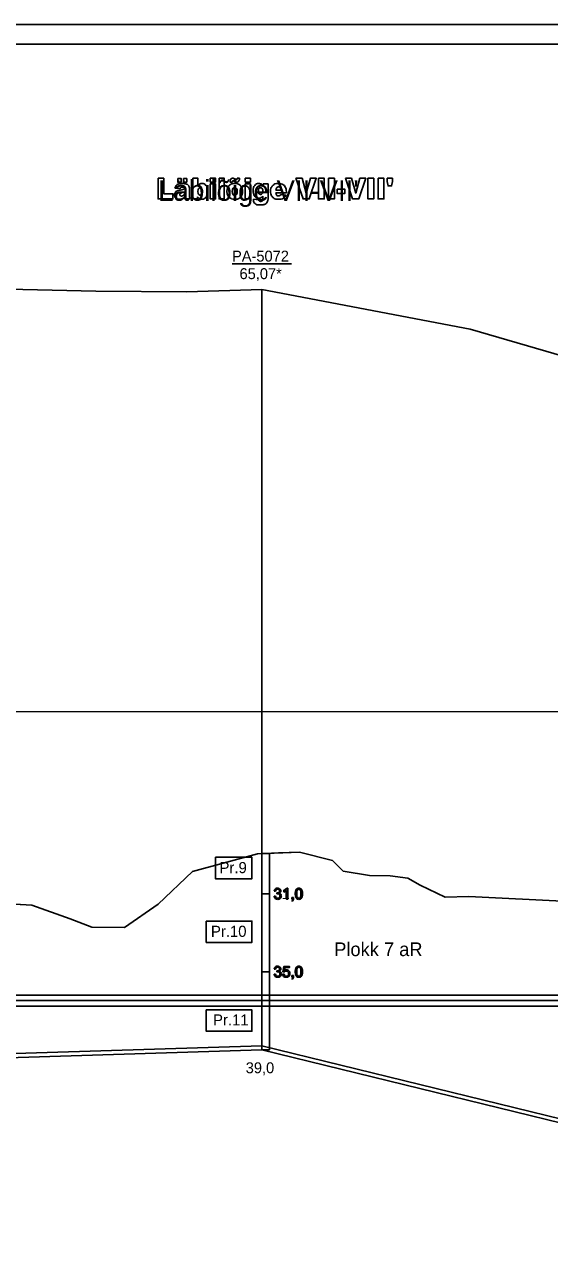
# Model space of a CAD drawing. Extents: x 700746 to 706058, y 6570320 to 6580460.
# Drawn here: x 704794 to 705063, y 6574741 to 6575370 of the extents above; entities that cross this region are included whole.
import ezdxf

# ---------------------------------------------------------------- set-up
doc = ezdxf.new("R2010")
doc.units = 0
for name, color, linetype in [('ABIJOONIS', 7, 'Continuous'), ('GEOLPUNKT', 7, 'Continuous'), ('GEOLPUNKT_proovid', 7, 'Continuous'), ('Lõige', 7, 'Continuous'), ('Maapind', 7, 'Continuous'), ('PIIR', 7, 'Continuous'), ('Plokid', 7, 'Continuous'), ('Täide', 7, 'Continuous'), ('VEEKOGU', 7, 'Continuous'), ('VORMISTUS', 7, 'Continuous')]:
    doc.layers.add(name, color=color, linetype=linetype)

# ---------------------------------------------------------------- blocks, each defined once
blk = doc.blocks.new("Läbilõige VII-VII'")
at = {"layer": 'Lõige'}
for points in [[(-30.27, 3.15), (-28.79, 3.15), (-28.79, -0.84), (-26.47, -0.84), (-26.47, -2.15), (-30.27, -2.15), (-30.27, 3.15)], [(-21.39, 3.15), (-20.05, 3.15), (-20.05, 1.31)], [(-20.15, -1.58), (-20.15, -2.15), (-21.39, -2.15), (-21.39, 3.15)], [(-16.88, 3.15), (-15.54, 3.15), (-15.54, 2.15), (-16.88, 2.15), (-16.88, 3.15)], [(-14.65, 3.15), (-13.31, 3.15), (-13.31, -2.15), (-14.65, -2.15), (-14.65, 3.15)], [(-9.96, 3.16), (-9.44, 3.16)], [(-7.93, 3.15), (-6.59, 3.15), (-6.59, 2.15), (-7.93, 2.15), (-7.93, 3.15)], [(5.06, 3.15), (6.61, 3.15), (7.69, -0.66), (8.76, 3.15), (10.26, 3.15), (8.48, -2.15), (6.87, -2.15), (5.06, 3.15)], [(10.81, 3.15), (12.3, 3.15), (12.3, -2.15), (10.81, -2.15), (10.81, 3.15)], [(13.42, 3.15), (14.91, 3.15), (14.91, -2.15), (13.42, -2.15), (13.42, 3.15)], [(17.73, 3.15), (19.29, 3.15), (20.37, -0.66), (21.44, 3.15), (22.94, 3.15), (21.16, -2.15), (19.55, -2.15), (17.73, 3.15)], [(23.49, 3.15), (24.98, 3.15), (24.98, -2.15), (23.49, -2.15), (23.49, 3.15)], [(26.1, 3.15), (27.59, 3.15), (27.59, -2.15), (26.1, -2.15), (26.1, 3.15)], [(28.44, 3.15), (29.77, 3.15), (29.77, 2.28), (29.56, 1.2), (28.66, 1.2), (28.44, 2.28), (28.44, 3.15)], [(-24.66, 0.44), (-25.94, 0.59)], [(-25.17, 3.08), (-24.32, 3.08), (-24.32, 2.18), (-25.17, 2.18), (-25.17, 3.08)], [(-23.79, 3.08), (-22.93, 3.08), (-22.93, 2.18), (-23.79, 2.18), (-23.79, 3.08)], [(-22.21, 0.36), (-22.21, -1.33)], [(-16.88, 1.69), (-15.54, 1.69), (-15.54, -2.15), (-16.88, -2.15), (-16.88, 1.69)], [(-11.29, 2.16), (-11.8, 2.16)], [(-7.93, 1.69), (-6.59, 1.69), (-6.59, -2.15), (-7.93, -2.15), (-7.93, 1.69)], [(-3.32, 1.69), (-2.07, 1.69), (-2.07, -1.93), (-2.07, -2.1)], [(-3.32, 1.12), (-3.32, 1.69)], [(-0.07, 0.11), (1.24, 0.11)], [(15.63, 0.35), (17.57, 0.35), (17.57, -0.79), (15.63, -0.79), (15.63, 0.35)], [(-23.51, -0.56), (-23.51, -0.33)], [(-22.04, -2.15), (-23.29, -2.15)], [(-5.8, -2.24), (-4.51, -2.4)], [(-3.42, -2.02), (-3.42, -1.44)], [(2.6, -0.59), (-0.07, -0.59)], [(1.21, -1.02), (2.52, -1.16)], [(2.6, -0.43), (2.6, -0.59)]]:
    blk.add_lwpolyline(points, dxfattribs=at)
for points in [[(-11.8, 2.16), (-11.8, 2.25), (-11.8, 2.31), (-11.8, 2.7), (-11.61, 2.93), (-11.42, 3.16), (-11.15, 3.16), (-11.04, 3.16), (-10.94, 3.13), (-10.83, 3.1), (-10.56, 2.97), (-10.29, 2.84), (-10.16, 2.84), (-10.08, 2.84), (-10.02, 2.91), (-9.97, 2.98), (-9.96, 3.16)], [(-9.44, 3.16), (-9.44, 3.06), (-9.44, 2.99), (-9.44, 2.59), (-9.62, 2.37), (-9.81, 2.15), (-10.09, 2.15), (-10.3, 2.15), (-10.73, 2.34), (-10.99, 2.46), (-11.08, 2.46), (-11.18, 2.46), (-11.23, 2.39), (-11.28, 2.33), (-11.29, 2.16)], [(-23.29, -2.15), (-23.37, -2), (-23.39, -1.92), (-23.41, -1.85), (-23.44, -1.68), (-23.7, -1.96), (-23.96, -2.08), (-24.31, -2.24), (-24.78, -2.24), (-25.4, -2.24), (-25.72, -1.92), (-26.04, -1.6), (-26.04, -1.14), (-26.04, -0.7), (-25.81, -0.42), (-25.58, -0.13), (-24.95, 0), (-24.2, 0.17), (-23.98, 0.24), (-23.76, 0.3), (-23.51, 0.41), (-23.51, 0.68), (-23.61, 0.79), (-23.71, 0.9), (-23.97, 0.9), (-24.29, 0.9), (-24.46, 0.78), (-24.58, 0.69), (-24.66, 0.44)], [(-25.94, 0.59), (-25.86, 0.96), (-25.73, 1.17), (-25.59, 1.39), (-25.34, 1.54), (-25.15, 1.65), (-24.83, 1.72), (-24.51, 1.78), (-24.14, 1.78), (-23.54, 1.78), (-23.18, 1.7), (-22.82, 1.63), (-22.57, 1.39), (-22.4, 1.23), (-22.31, 0.93), (-22.21, 0.63), (-22.21, 0.36)], [(-20.05, 1.31), (-19.85, 1.55), (-19.6, 1.66), (-19.34, 1.78), (-19.04, 1.78), (-18.4, 1.78), (-17.99, 1.27), (-17.57, 0.77), (-17.57, -0.18), (-17.57, -0.8), (-17.76, -1.28), (-17.95, -1.76), (-18.28, -2), (-18.62, -2.24), (-19.03, -2.24), (-19.38, -2.24), (-19.67, -2.07), (-19.89, -1.94), (-20.15, -1.58)], [(-20.06, -0.22), (-20.06, -0.72), (-19.89, -0.94), (-19.72, -1.16), (-19.47, -1.16), (-19.23, -1.16), (-19.07, -0.94), (-18.9, -0.72), (-18.9, -0.21), (-18.9, 0.25), (-19.06, 0.46), (-19.22, 0.68), (-19.45, 0.68), (-19.72, 0.68), (-19.89, 0.45), (-20.06, 0.23), (-20.06, -0.22)], [(-12.62, -0.24), (-12.62, 0.64), (-12.08, 1.21), (-11.54, 1.78), (-10.63, 1.78), (-9.59, 1.78), (-9.05, 1.11), (-8.63, 0.57), (-8.63, -0.22), (-8.63, -1.1), (-9.16, -1.67), (-9.69, -2.24), (-10.63, -2.24), (-11.47, -2.24), (-11.98, -1.77), (-12.62, -1.18), (-12.62, -0.24)], [(-11.28, -0.24), (-11.28, -0.75), (-11.09, -1), (-10.91, -1.24), (-10.62, -1.24), (-10.33, -1.24), (-10.15, -1), (-9.97, -0.76), (-9.97, -0.22), (-9.97, 0.28), (-10.15, 0.52), (-10.34, 0.76), (-10.61, 0.76), (-10.9, 0.76), (-11.09, 0.52), (-11.28, 0.27), (-11.28, -0.24)], [(-3.42, -1.44), (-3.62, -1.7), (-3.81, -1.82), (-4.12, -2), (-4.48, -2), (-5.17, -2), (-5.6, -1.32), (-5.9, -0.85), (-5.9, -0.06), (-5.9, 0.84), (-5.51, 1.31), (-5.12, 1.78), (-4.49, 1.78), (-4.08, 1.78), (-3.82, 1.63), (-3.55, 1.47), (-3.32, 1.12)], [(-4.57, -0.17), (-4.57, -0.59), (-4.41, -0.79), (-4.25, -0.99), (-3.99, -0.99), (-3.75, -0.99), (-3.58, -0.78), (-3.41, -0.58), (-3.41, -0.15), (-3.41, 0.27), (-3.59, 0.49), (-3.76, 0.71), (-4.02, 0.71), (-4.27, 0.71), (-4.42, 0.51), (-4.57, 0.3), (-4.57, -0.17)], [(2.52, -1.16), (2.22, -1.73), (1.79, -1.99), (1.37, -2.24), (0.57, -2.24), (-0.12, -2.24), (-0.52, -2.02), (-0.91, -1.81), (-1.17, -1.34), (-1.43, -0.87), (-1.43, -0.24), (-1.43, 0.66), (-0.91, 1.22), (-0.39, 1.78), (0.53, 1.78), (1.28, 1.78), (1.71, 1.53), (2.14, 1.28), (2.37, 0.81), (2.6, 0.33), (2.6, -0.43)], [(1.24, 0.11), (1.2, 0.54), (1.03, 0.72), (0.86, 0.91), (0.59, 0.91), (0.27, 0.91), (0.08, 0.63), (-0.04, 0.45), (-0.07, 0.11)], [(-23.51, -0.33), (-23.79, -0.44), (-24.08, -0.52), (-24.49, -0.64), (-24.6, -0.76), (-24.71, -0.87), (-24.71, -1.03), (-24.71, -1.2), (-24.6, -1.31), (-24.49, -1.42), (-24.28, -1.42), (-24.05, -1.42), (-23.86, -1.3), (-23.67, -1.18), (-23.59, -1.01), (-23.51, -0.84), (-23.51, -0.56)], [(-22.21, -1.33), (-22.21, -1.6), (-22.18, -1.76), (-22.15, -1.91), (-22.04, -2.15)], [(-2.07, -2.1), (-2.07, -2.47), (-2.21, -2.79), (-2.35, -3.12), (-2.58, -3.32), (-2.81, -3.53), (-3.17, -3.62), (-3.52, -3.71), (-3.98, -3.71), (-5.03, -3.71), (-5.42, -3.36), (-5.81, -3.01), (-5.81, -2.43), (-5.81, -2.36), (-5.8, -2.24)], [(-4.51, -2.4), (-4.46, -2.6), (-4.36, -2.67), (-4.21, -2.78), (-3.99, -2.78), (-3.7, -2.78), (-3.56, -2.61), (-3.42, -2.44), (-3.42, -2.02)], [(-0.07, -0.59), (-0.04, -0.95), (0.1, -1.12), (0.29, -1.37), (0.6, -1.37), (0.8, -1.37), (0.98, -1.27), (1.09, -1.2), (1.21, -1.02)]]:
    blk.add_open_spline(points, degree=3, dxfattribs=at)
blk.add_text("Läbilõige VII-VII'", height=5.3, dxfattribs=at).set_placement((-30.26, -2.65))

msp = doc.modelspace()

# ---------------------------------------------------------------- linework, layer by layer
at = {"layer": 'ABIJOONIS'}
msp.add_lwpolyline([(704017.06, 6575370.2), (705897.06, 6575370.2), (705897.06, 6574500.2), (704017.06, 6574500.2), (704017.06, 6575370.2)], dxfattribs=at)
at = {"layer": 'GEOLPUNKT'}
for p, q in [((704900.75, 6575247.41), (704931.19, 6575247.41)), ((704915.95, 6575234.43), (704915.95, 6574945.02)), ((704915.95, 6574945.02), (704915.95, 6574844.43))]:
    msp.add_line(p, q, dxfattribs=at)
at = {"layer": 'GEOLPUNKT_proovid'}
for points in [[(704915.95, 6574945.02), (704919.95, 6574945.02), (704919.95, 6574924.43), (704915.95, 6574924.43)], [(704892.25, 6574943.09), (704910.95, 6574943.09), (704910.95, 6574932.13), (704892.25, 6574932.13)], [(704915.95, 6574924.43), (704919.95, 6574924.43), (704919.95, 6574884.43), (704915.95, 6574884.43)], [(704887.53, 6574910.38), (704910.95, 6574910.38), (704910.95, 6574899.42), (704887.53, 6574899.42)], [(704915.95, 6574884.43), (704919.95, 6574884.43), (704919.95, 6574844.43), (704915.95, 6574844.43)], [(704887.53, 6574864.86), (704910.95, 6574864.86), (704910.95, 6574853.9), (704887.53, 6574853.9)]]:
    msp.add_lwpolyline(points, close=True, dxfattribs=at)
for points in [[(704923.08, 6574925.68), (704922.39, 6574925.8)], [(704927.2, 6574925.18), (704927.2, 6574925.84)], [(704929.26, 6574921.63), (704928.57, 6574921.63), (704928.57, 6574926.01)], [(704928.81, 6574927.25), (704929.26, 6574927.25), (704929.26, 6574921.63)], [(704922.33, 6574923.11), (704923.01, 6574923.2)], [(704923.68, 6574924.28), (704923.76, 6574924.89)], [(704931.54, 6574920.52), (704931.34, 6574920.81)], [(704931.39, 6574921.63), (704931.39, 6574922.41), (704932.17, 6574922.41), (704932.17, 6574921.63)], [(704931.78, 6574921.63), (704931.39, 6574921.63)], [(704922.33, 6574883.11), (704923.01, 6574883.2)], [(704923.08, 6574885.68), (704922.39, 6574885.8)], [(704923.68, 6574884.28), (704923.76, 6574884.89)], [(704926.67, 6574883.1), (704927.39, 6574883.16)], [(704927.44, 6574884.19), (704926.79, 6574884.28), (704927.34, 6574887.16), (704930.12, 6574887.16), (704930.12, 6574886.5), (704927.89, 6574886.5), (704927.58, 6574885)], [(704931.39, 6574881.63), (704931.39, 6574882.41), (704932.17, 6574882.41), (704932.17, 6574881.63)], [(704931.54, 6574880.52), (704931.34, 6574880.81)], [(704931.78, 6574881.63), (704931.39, 6574881.63)]]:
    msp.add_lwpolyline(points, dxfattribs=at)
for points in [[(704922.39, 6574925.8), (704922.52, 6574926.49), (704922.97, 6574926.87), (704923.41, 6574927.25), (704924.08, 6574927.25), (704924.54, 6574927.25), (704924.92, 6574927.05), (704925.31, 6574926.86), (704925.51, 6574926.52), (704925.72, 6574926.18), (704925.72, 6574925.8), (704925.72, 6574925.44), (704925.52, 6574925.14), (704925.33, 6574924.84), (704924.95, 6574924.66), (704925.44, 6574924.55), (704925.72, 6574924.19), (704925.99, 6574923.83), (704925.99, 6574923.29), (704925.99, 6574922.55), (704925.46, 6574922.04), (704924.92, 6574921.54), (704924.11, 6574921.54), (704923.37, 6574921.54), (704922.88, 6574921.97), (704922.39, 6574922.41), (704922.33, 6574923.11)], [(704923.76, 6574924.89), (704923.83, 6574924.88), (704923.87, 6574924.88), (704924.31, 6574924.88), (704924.66, 6574925.11), (704925.01, 6574925.34), (704925.01, 6574925.81), (704925.01, 6574926.19), (704924.75, 6574926.44), (704924.5, 6574926.69), (704924.09, 6574926.69), (704923.69, 6574926.69), (704923.42, 6574926.43), (704923.16, 6574926.18), (704923.08, 6574925.68)], [(704927.2, 6574925.84), (704927.77, 6574926.12), (704928.2, 6574926.5), (704928.64, 6574926.89), (704928.81, 6574927.25)], [(704928.57, 6574926.01), (704928.32, 6574925.77), (704927.92, 6574925.54), (704927.52, 6574925.3), (704927.2, 6574925.18)], [(704933.19, 6574924.39), (704933.19, 6574925.38), (704933.4, 6574925.99), (704933.6, 6574926.6), (704934, 6574926.92), (704934.41, 6574927.25), (704935.02, 6574927.25), (704935.47, 6574927.25), (704935.81, 6574927.07), (704936.15, 6574926.89), (704936.37, 6574926.55), (704936.59, 6574926.2), (704936.72, 6574925.71), (704936.84, 6574925.22), (704936.84, 6574924.39), (704936.84, 6574923.41), (704936.64, 6574922.8), (704936.44, 6574922.19), (704936.03, 6574921.86), (704935.63, 6574921.54), (704935.02, 6574921.54), (704934.21, 6574921.54), (704933.75, 6574922.11), (704933.19, 6574922.81), (704933.19, 6574924.39)], [(704933.9, 6574924.39), (704933.9, 6574923.01), (704934.22, 6574922.55), (704934.55, 6574922.1), (704935.02, 6574922.1), (704935.49, 6574922.1), (704935.81, 6574922.56), (704936.13, 6574923.01), (704936.13, 6574924.39), (704936.13, 6574925.77), (704935.81, 6574926.23), (704935.49, 6574926.68), (704935.01, 6574926.68), (704934.54, 6574926.68), (704934.25, 6574926.28), (704933.9, 6574925.77), (704933.9, 6574924.39)], [(704923.01, 6574923.2), (704923.13, 6574922.62), (704923.41, 6574922.36), (704923.7, 6574922.1), (704924.11, 6574922.1), (704924.6, 6574922.1), (704924.93, 6574922.44), (704925.26, 6574922.77), (704925.26, 6574923.27), (704925.26, 6574923.75), (704924.95, 6574924.05), (704924.64, 6574924.36), (704924.17, 6574924.36), (704923.97, 6574924.36), (704923.68, 6574924.28)], [(704931.34, 6574920.81), (704931.56, 6574920.91), (704931.67, 6574921.1), (704931.77, 6574921.28), (704931.78, 6574921.63)], [(704932.17, 6574921.63), (704932.17, 6574921.2), (704932.02, 6574920.93), (704931.87, 6574920.66), (704931.54, 6574920.52)], [(704922.39, 6574885.8), (704922.52, 6574886.49), (704922.97, 6574886.87), (704923.41, 6574887.25), (704924.08, 6574887.25), (704924.54, 6574887.25), (704924.92, 6574887.05), (704925.31, 6574886.86), (704925.51, 6574886.52), (704925.72, 6574886.18), (704925.72, 6574885.8), (704925.72, 6574885.44), (704925.52, 6574885.14), (704925.33, 6574884.84), (704924.95, 6574884.66), (704925.44, 6574884.55), (704925.72, 6574884.19), (704925.99, 6574883.83), (704925.99, 6574883.29), (704925.99, 6574882.55), (704925.46, 6574882.04), (704924.92, 6574881.54), (704924.11, 6574881.54), (704923.37, 6574881.54), (704922.88, 6574881.97), (704922.39, 6574882.41), (704922.33, 6574883.11)], [(704923.01, 6574883.2), (704923.13, 6574882.62), (704923.41, 6574882.36), (704923.7, 6574882.1), (704924.11, 6574882.1), (704924.6, 6574882.1), (704924.93, 6574882.44), (704925.26, 6574882.77), (704925.26, 6574883.27), (704925.26, 6574883.75), (704924.95, 6574884.05), (704924.64, 6574884.36), (704924.17, 6574884.36), (704923.97, 6574884.36), (704923.68, 6574884.28)], [(704923.76, 6574884.89), (704923.83, 6574884.88), (704923.87, 6574884.88), (704924.31, 6574884.88), (704924.66, 6574885.11), (704925.01, 6574885.34), (704925.01, 6574885.81), (704925.01, 6574886.19), (704924.75, 6574886.44), (704924.5, 6574886.69), (704924.09, 6574886.69), (704923.69, 6574886.69), (704923.42, 6574886.43), (704923.16, 6574886.18), (704923.08, 6574885.68)], [(704927.58, 6574885), (704928.09, 6574885.35), (704928.64, 6574885.35), (704929.38, 6574885.35), (704929.88, 6574884.84), (704930.38, 6574884.33), (704930.38, 6574883.53), (704930.38, 6574882.77), (704929.94, 6574882.22), (704929.4, 6574881.54), (704928.47, 6574881.54), (704927.71, 6574881.54), (704927.22, 6574881.96), (704926.74, 6574882.39), (704926.67, 6574883.1)], [(704927.39, 6574883.16), (704927.47, 6574882.63), (704927.76, 6574882.36), (704928.05, 6574882.1), (704928.47, 6574882.1), (704928.97, 6574882.1), (704929.31, 6574882.47), (704929.65, 6574882.85), (704929.65, 6574883.47), (704929.65, 6574884.06), (704929.33, 6574884.4), (704929, 6574884.74), (704928.46, 6574884.74), (704928.12, 6574884.74), (704927.86, 6574884.59), (704927.59, 6574884.44), (704927.44, 6574884.19)], [(704933.19, 6574884.39), (704933.19, 6574885.38), (704933.4, 6574885.99), (704933.6, 6574886.6), (704934, 6574886.92), (704934.41, 6574887.25), (704935.02, 6574887.25), (704935.47, 6574887.25), (704935.81, 6574887.07), (704936.15, 6574886.89), (704936.37, 6574886.55), (704936.59, 6574886.2), (704936.72, 6574885.71), (704936.84, 6574885.22), (704936.84, 6574884.39), (704936.84, 6574883.41), (704936.64, 6574882.8), (704936.44, 6574882.19), (704936.03, 6574881.86), (704935.63, 6574881.54), (704935.02, 6574881.54), (704934.21, 6574881.54), (704933.75, 6574882.11), (704933.19, 6574882.81), (704933.19, 6574884.39)], [(704933.9, 6574884.39), (704933.9, 6574883.01), (704934.22, 6574882.55), (704934.55, 6574882.1), (704935.02, 6574882.1), (704935.49, 6574882.1), (704935.81, 6574882.56), (704936.13, 6574883.01), (704936.13, 6574884.39), (704936.13, 6574885.77), (704935.81, 6574886.23), (704935.49, 6574886.68), (704935.01, 6574886.68), (704934.54, 6574886.68), (704934.25, 6574886.28), (704933.9, 6574885.77), (704933.9, 6574884.39)], [(704931.34, 6574880.81), (704931.56, 6574880.91), (704931.67, 6574881.1), (704931.77, 6574881.28), (704931.78, 6574881.63)], [(704932.17, 6574881.63), (704932.17, 6574881.2), (704932.02, 6574880.93), (704931.87, 6574880.66), (704931.54, 6574880.52)]]:
    msp.add_open_spline(points, degree=3, dxfattribs=at)
at = {"layer": 'Lõige'}
msp.add_lwpolyline([(704679.17, 6575234.86), (704714.61, 6575235.14), (704778.45, 6575234.57), (704830.93, 6575233.51), (704877.56, 6575233.07), (704915.99, 6575234.23), (705022.75, 6575213.95), (705104.45, 6575190.26), (705146.87, 6575177.81), (705170.34, 6575173.32), (705231.69, 6575175.91), (705287.59, 6575182.15), (705361.43, 6575192.97), (705409.56, 6575198.3), (705432.36, 6575196.11)], dxfattribs=at)
at = {"layer": 'Maapind'}
msp.add_lwpolyline([(705118.38, 6574794.81), (704915.95, 6574844.43), (704720.42, 6574838.24)], dxfattribs=at)
at = {"layer": 'PIIR'}
msp.add_lwpolyline([(704401.55, 6574869.63), (705660.11, 6574869.63)], dxfattribs=at)
at = {"layer": 'Plokid'}
for p, q in [((704401.55, 6574872.38), (705659.86, 6574872.38)), ((704146.26, 6574866.83), (705645.04, 6574866.83))]:
    msp.add_line(p, q, dxfattribs=at)
for points in [[(705073.51, 6574920.41), (705022.04, 6574922.92), (705009.96, 6574922.69), (704997.06, 6574928.76), (704990.74, 6574932.45), (704981.71, 6574933.66), (704971.24, 6574933.82), (704957.61, 6574936.05), (704952.22, 6574941.43), (704935.35, 6574945.71), (704913.85, 6574944.94), (704880.52, 6574935.85), (704862.93, 6574919.13), (704845.56, 6574907.06), (704828.81, 6574907.28), (704817.74, 6574911.61), (704798.16, 6574918.57), (704772.04, 6574920.01)], [(704399.9, 6574813.93), (704646.39, 6574838.03), (704915.95, 6574846.43), (705118.38, 6574796.88), (705170.55, 6574795.33), (705409.93, 6574822.93), (705409.93, 6574822.93), (705409.93, 6574822.93), (705645.04, 6574866.83)]]:
    msp.add_lwpolyline(points, dxfattribs=at)
at = {"layer": 'Täide'}
for points in [[(705073.51, 6574920.41), (705022.04, 6574922.92), (705009.96, 6574922.69), (704997.06, 6574928.76), (704990.74, 6574932.45), (704981.71, 6574933.66), (704971.24, 6574933.82), (704957.61, 6574936.05), (704952.22, 6574941.43), (704935.35, 6574945.71), (704924.6, 6574945.33), (704913.85, 6574944.94), (704880.52, 6574935.85), (704862.93, 6574919.13), (704845.56, 6574907.06), (704828.81, 6574907.28), (704817.74, 6574911.61), (704798.16, 6574918.57), (704772.04, 6574920.01)], [(705073.51, 6574920.41), (705022.04, 6574922.92), (705009.96, 6574922.69), (704997.06, 6574928.76), (704990.74, 6574932.45), (704981.71, 6574933.66), (704971.24, 6574933.82), (704957.61, 6574936.05), (704952.22, 6574941.43), (704935.35, 6574945.71), (704924.6, 6574945.33), (704913.85, 6574944.94), (704880.52, 6574935.85), (704862.93, 6574919.13), (704845.56, 6574907.06), (704828.81, 6574907.28), (704817.74, 6574911.61), (704798.16, 6574918.57), (704772.04, 6574920.01)], [(704720.42, 6574838.24), (704915.95, 6574844.43), (705118.38, 6574794.81), (705170.55, 6574793.33), (705189.33, 6574795.03), (705409.93, 6574820.93), (705450.07, 6574821.41), (705658.33, 6574869.28)], [(704720.42, 6574838.24), (704915.95, 6574844.43), (705118.38, 6574794.81)]]:
    msp.add_lwpolyline(points, dxfattribs=at)
at = {"layer": 'VEEKOGU'}
for p, q in [((705306.43, 6575017.91), (704272.86, 6575017.6)), ((704880.52, 6574935.85), (704913.85, 6574944.94)), ((704957.61, 6574936.05), (704971.24, 6574933.82)), ((704772.04, 6574920.01), (704798.16, 6574918.57)), ((705022.04, 6574922.92), (705073.51, 6574920.41)), ((704798.16, 6574918.57), (704817.74, 6574911.61))]:
    msp.add_line(p, q, dxfattribs=at)
for points in [[(704913.85, 6574944.94), (704924.6, 6574945.33), (704935.35, 6574945.71), (704952.22, 6574941.43), (704957.61, 6574936.05)], [(704817.74, 6574911.61), (704828.81, 6574907.28), (704845.56, 6574907.06), (704862.93, 6574919.13), (704880.52, 6574935.85)], [(704971.24, 6574933.82), (704981.71, 6574933.66), (704990.74, 6574932.45), (704997.06, 6574928.76), (705009.96, 6574922.69), (705022.04, 6574922.92)]]:
    msp.add_lwpolyline(points, dxfattribs=at)
at = {"layer": 'VORMISTUS'}
msp.add_lwpolyline([(704057.06, 6574510.2), (705887.06, 6574510.2), (705887.06, 6575360.2), (704057.06, 6575360.2)], close=True, dxfattribs=at)

# ---------------------------------------------------------------- block references
at = {"layer": 'VORMISTUS', "xscale": 2, "yscale": 2}
msp.add_blockref("Läbilõige VII-VII'", (704923.36, 6575285.08), dxfattribs=at)

# ---------------------------------------------------------------- texts
at = {"layer": 'GEOLPUNKT'}
for s, p in [('PA-5072', (704900.73, 6575248.63)), ('65,07*', (704904.57, 6575239.63)), ('65,07*', (704904.57, 6575239.63)), ('39,0', (704907.75, 6574832.35))]:
    msp.add_text(s, height=5.6, dxfattribs=at).set_placement(p)
at = {"layer": 'GEOLPUNKT_proovid'}
for s, height, p in [('Pr.9', 5.7, (704894.32, 6574934.96)), ('31,0', 5.6, (704922, 6574921.63)), ('Pr.10', 5.7, (704889.92, 6574902.28)), ('35,0', 5.6, (704922, 6574881.63)), ('Pr.11', 5.7, (704891.01, 6574856.84))]:
    msp.add_text(s, height=height, dxfattribs=at).set_placement(p)
at = {"layer": 'Plokid'}
msp.add_text('Plokk 7 aR', height=7, dxfattribs=at).set_placement((704953.08, 6574892.43))

doc.saveas('drawing.dxf')
